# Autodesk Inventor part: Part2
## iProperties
Shininess: 77.0
Angle Display Precision: 2
Document Length Units: 11269
Document Angle Units: 11279
Document Time Units: 11290
Document Mass Units: 11283
Document Length Units Precision: 3
Document Angle Units Precision: 2
Created: 2001-12
Part Number: Part2
Document SubType Name: Modeling
Designer: Renu Muthoo
Density: 1 g/cm^3
Density: 0.0
Volumn: 0.0
Area: 0.0
PropertySet Name: Model Information
Control State: 0
Master: False
Checked Out: False
Author: Renu Muthoo
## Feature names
1. Extrusion1
2. Extrusion2
3. Extrusion3
4. Mirror1
5. Fillet1
6. Hole1
